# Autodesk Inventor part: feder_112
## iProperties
Created: 2008-12
Part Number: feder_112
Document SubType Name: Modeling
Designer: Wolfgang
Density: 1 g/cm^3
Author: Wolfgang
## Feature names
1. Extrusion1
2. Spirale2
3. Umdrehung1 [Revolution]
